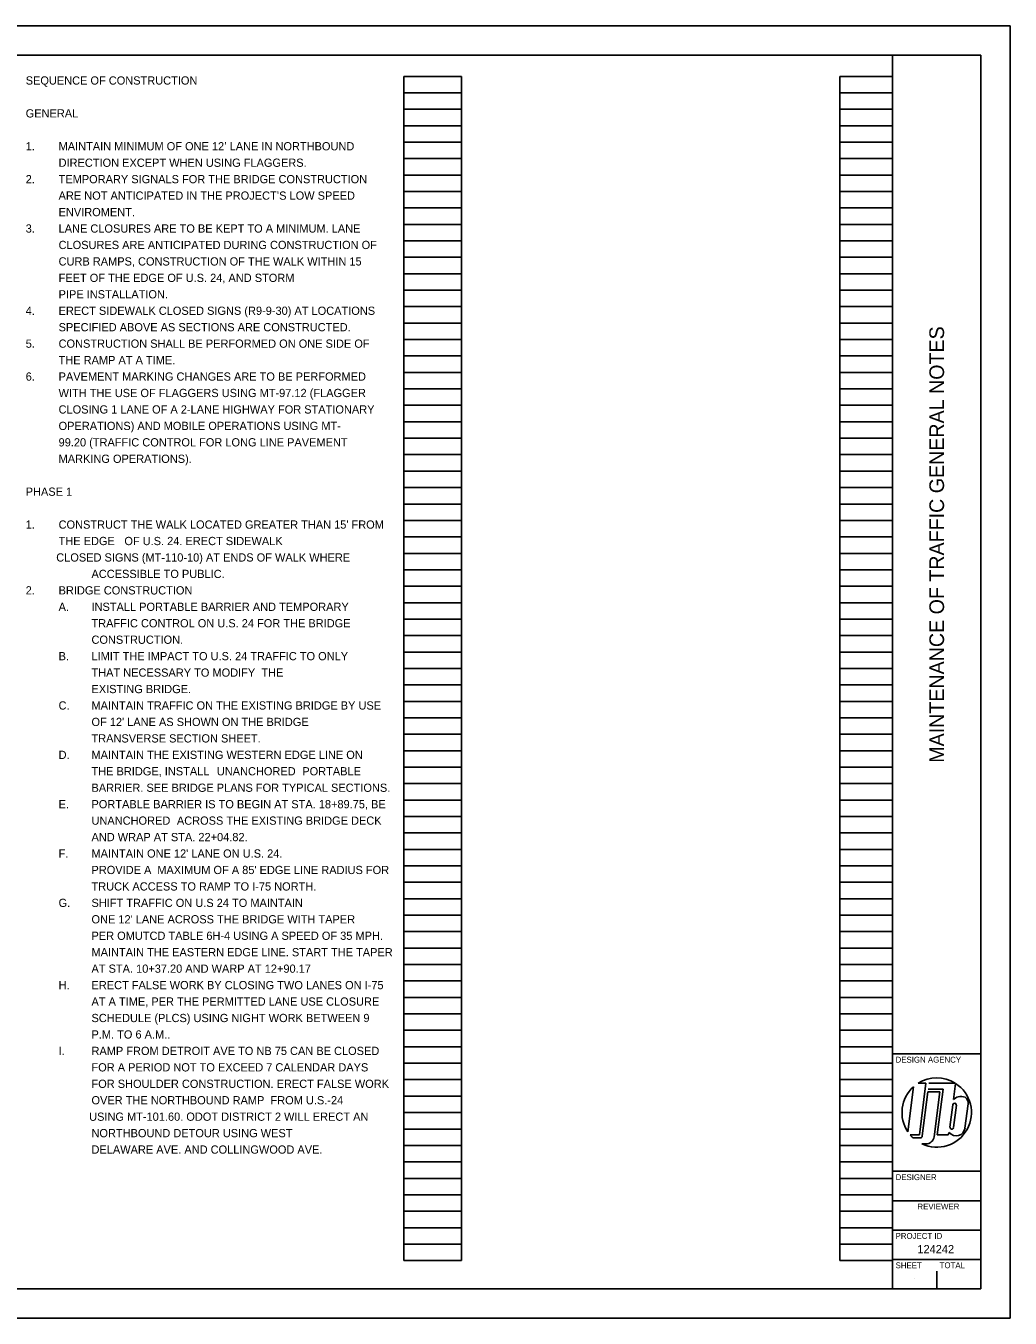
# Model space of a CAD drawing. Extents: x -43 to -9, y 0 to 22.
# Drawn here: x -25.8 to -9.05, y 0 to 22 of the extents above; entities that cross this region are included whole.
import ezdxf

# ---------------------------------------------------------------- set-up
doc = ezdxf.new("R2010")
doc.units = 0
for name, color, linetype in [('SC_Scratch1', 7, 'Continuous'), ('SC_Scratch2', 7, 'Continuous'), ('SH_Text', 7, 'Continuous')]:
    doc.layers.add(name, color=color, linetype=linetype)

msp = doc.modelspace()

# ---------------------------------------------------------------- linework, layer by layer
at = {"layer": 'SC_Scratch1'}
for p, q in [((-19.367, 0.98), (-19.367, 21.14)), ((-19.367, 21.14), (-18.387, 21.14)), ((-18.387, 0.98), (-18.387, 21.14)), ((-11.947, 0.98), (-11.947, 21.14)), ((-11.947, 21.14), (-11.047, 21.14)), ((-11.047, 0.98), (-11.047, 21.14)), ((-19.367, 20.86), (-18.387, 20.86)), ((-11.947, 20.86), (-11.047, 20.86)), ((-19.367, 20.58), (-18.387, 20.58)), ((-11.947, 20.58), (-11.047, 20.58)), ((-19.367, 20.3), (-18.387, 20.3)), ((-11.947, 20.3), (-11.047, 20.3)), ((-19.367, 20.02), (-18.387, 20.02)), ((-11.947, 20.02), (-11.047, 20.02)), ((-19.367, 19.74), (-18.387, 19.74)), ((-11.947, 19.74), (-11.047, 19.74)), ((-19.367, 19.46), (-18.387, 19.46)), ((-11.947, 19.46), (-11.047, 19.46)), ((-19.367, 19.18), (-18.387, 19.18)), ((-11.947, 19.18), (-11.047, 19.18)), ((-19.367, 18.9), (-18.387, 18.9)), ((-11.947, 18.9), (-11.047, 18.9)), ((-19.367, 18.62), (-18.387, 18.62)), ((-11.947, 18.62), (-11.047, 18.62)), ((-19.367, 18.34), (-18.387, 18.34)), ((-11.947, 18.34), (-11.047, 18.34)), ((-19.367, 18.06), (-18.387, 18.06)), ((-11.947, 18.06), (-11.047, 18.06)), ((-19.367, 17.78), (-18.387, 17.78)), ((-11.947, 17.78), (-11.047, 17.78)), ((-19.367, 17.5), (-18.387, 17.5)), ((-11.947, 17.5), (-11.047, 17.5)), ((-19.367, 17.22), (-18.387, 17.22)), ((-11.947, 17.22), (-11.047, 17.22)), ((-19.367, 16.94), (-18.387, 16.94)), ((-11.947, 16.94), (-11.047, 16.94)), ((-19.367, 16.66), (-18.387, 16.66)), ((-11.947, 16.66), (-11.047, 16.66)), ((-19.367, 16.38), (-18.387, 16.38)), ((-11.947, 16.38), (-11.047, 16.38)), ((-19.367, 16.1), (-18.387, 16.1)), ((-11.947, 16.1), (-11.047, 16.1)), ((-19.367, 15.82), (-18.387, 15.82)), ((-11.947, 15.82), (-11.047, 15.82)), ((-19.367, 15.54), (-18.387, 15.54)), ((-11.947, 15.54), (-11.047, 15.54)), ((-19.367, 15.26), (-18.387, 15.26)), ((-11.947, 15.26), (-11.047, 15.26)), ((-19.367, 14.98), (-18.387, 14.98)), ((-11.947, 14.98), (-11.047, 14.98)), ((-19.367, 14.7), (-18.387, 14.7)), ((-11.947, 14.7), (-11.047, 14.7)), ((-19.367, 14.42), (-18.387, 14.42)), ((-11.947, 14.42), (-11.047, 14.42)), ((-19.367, 14.14), (-18.387, 14.14)), ((-11.947, 14.14), (-11.047, 14.14)), ((-19.367, 13.86), (-18.387, 13.86)), ((-11.947, 13.86), (-11.047, 13.86)), ((-19.367, 13.58), (-18.387, 13.58)), ((-11.947, 13.58), (-11.047, 13.58)), ((-19.367, 13.3), (-18.387, 13.3)), ((-11.947, 13.3), (-11.047, 13.3)), ((-19.367, 13.02), (-18.387, 13.02)), ((-11.947, 13.02), (-11.047, 13.02)), ((-19.367, 12.74), (-18.387, 12.74)), ((-11.947, 12.74), (-11.047, 12.74)), ((-19.367, 12.46), (-18.387, 12.46)), ((-11.947, 12.46), (-11.047, 12.46)), ((-19.367, 12.18), (-18.387, 12.18)), ((-11.947, 12.18), (-11.047, 12.18)), ((-19.367, 11.9), (-18.387, 11.9)), ((-11.947, 11.9), (-11.047, 11.9)), ((-19.367, 11.62), (-18.387, 11.62)), ((-11.947, 11.62), (-11.047, 11.62)), ((-19.367, 11.34), (-18.387, 11.34)), ((-11.947, 11.34), (-11.047, 11.34)), ((-19.367, 11.06), (-18.387, 11.06)), ((-11.947, 11.06), (-11.047, 11.06)), ((-19.367, 10.78), (-18.387, 10.78)), ((-11.947, 10.78), (-11.047, 10.78)), ((-19.367, 10.5), (-18.387, 10.5)), ((-11.947, 10.5), (-11.047, 10.5)), ((-19.367, 10.22), (-18.387, 10.22)), ((-11.947, 10.22), (-11.047, 10.22)), ((-19.367, 9.94), (-18.387, 9.94)), ((-11.947, 9.94), (-11.047, 9.94)), ((-19.367, 9.66), (-18.387, 9.66)), ((-11.947, 9.66), (-11.047, 9.66)), ((-19.367, 9.38), (-18.387, 9.38)), ((-11.947, 9.38), (-11.047, 9.38)), ((-19.367, 9.1), (-18.387, 9.1)), ((-11.947, 9.1), (-11.047, 9.1)), ((-19.367, 8.82), (-18.387, 8.82)), ((-11.947, 8.82), (-11.047, 8.82)), ((-19.367, 8.54), (-18.387, 8.54)), ((-11.947, 8.54), (-11.047, 8.54)), ((-19.367, 8.26), (-18.387, 8.26)), ((-11.947, 8.26), (-11.047, 8.26)), ((-19.367, 7.98), (-18.387, 7.98)), ((-11.947, 7.98), (-11.047, 7.98)), ((-19.367, 7.7), (-18.387, 7.7)), ((-11.947, 7.7), (-11.047, 7.7)), ((-19.367, 7.42), (-18.387, 7.42)), ((-11.947, 7.42), (-11.047, 7.42)), ((-19.367, 7.14), (-18.387, 7.14)), ((-11.947, 7.14), (-11.047, 7.14)), ((-19.367, 6.86), (-18.387, 6.86)), ((-11.947, 6.86), (-11.047, 6.86)), ((-19.367, 6.58), (-18.387, 6.58)), ((-11.947, 6.58), (-11.047, 6.58)), ((-19.367, 6.3), (-18.387, 6.3)), ((-11.947, 6.3), (-11.047, 6.3)), ((-19.367, 6.02), (-18.387, 6.02)), ((-11.947, 6.02), (-11.047, 6.02)), ((-19.367, 5.74), (-18.387, 5.74)), ((-11.947, 5.74), (-11.047, 5.74)), ((-19.367, 5.46), (-18.387, 5.46)), ((-11.947, 5.46), (-11.047, 5.46)), ((-19.367, 5.18), (-18.387, 5.18)), ((-11.947, 5.18), (-11.047, 5.18)), ((-19.367, 4.9), (-18.387, 4.9)), ((-11.947, 4.9), (-11.047, 4.9)), ((-19.367, 4.62), (-18.387, 4.62)), ((-11.947, 4.62), (-11.047, 4.62)), ((-19.367, 4.34), (-18.387, 4.34)), ((-11.947, 4.34), (-11.047, 4.34)), ((-19.367, 4.06), (-18.387, 4.06)), ((-11.947, 4.06), (-11.047, 4.06)), ((-19.367, 3.78), (-18.387, 3.78)), ((-11.947, 3.78), (-11.047, 3.78)), ((-19.367, 3.5), (-18.387, 3.5)), ((-11.947, 3.5), (-11.047, 3.5)), ((-19.367, 3.22), (-18.387, 3.22)), ((-11.947, 3.22), (-11.047, 3.22)), ((-19.367, 2.94), (-18.387, 2.94)), ((-11.947, 2.94), (-11.047, 2.94)), ((-19.367, 2.66), (-18.387, 2.66)), ((-11.947, 2.66), (-11.047, 2.66)), ((-19.367, 2.38), (-18.387, 2.38)), ((-11.947, 2.38), (-11.047, 2.38)), ((-19.367, 2.1), (-18.387, 2.1)), ((-11.947, 2.1), (-11.047, 2.1)), ((-19.367, 1.82), (-18.387, 1.82)), ((-11.947, 1.82), (-11.047, 1.82)), ((-19.367, 1.54), (-18.387, 1.54)), ((-11.947, 1.54), (-11.047, 1.54)), ((-19.367, 1.26), (-18.387, 1.26)), ((-11.947, 1.26), (-11.047, 1.26)), ((-19.367, 0.98), (-18.387, 0.98)), ((-11.947, 0.98), (-11.047, 0.98))]:
    msp.add_line(p, q, dxfattribs=at)
at = {"layer": 'SC_Scratch2'}
for p, q in [((-11.047, 0.5), (-11.047, 21.5)), ((-11.047, 4.5), (-9.547, 4.5)), ((-10.615, 3.998), (-10.48, 3.998)), ((-10.48, 3.998), (-10.591, 3.118)), ((-10.43, 4), (-9.982, 4)), ((-9.977, 3.996), (-10.011, 3.72)), ((-10.691, 3.94), (-10.788, 3.171)), ((-10.543, 3.104), (-10.448, 3.855)), ((-10.448, 3.855), (-10.246, 3.855)), ((-10.19, 3.896), (-10.443, 3.896)), ((-10.246, 3.855), (-10.343, 3.089)), ((-10.289, 3.118), (-10.19, 3.896)), ((-10.023, 3.631), (-10.071, 3.25)), ((-10.011, 3.243), (-9.963, 3.624)), ((-9.764, 3.648), (-9.816, 3.237)), ((-10.297, 3.5), (-10.297, 3.5)), ((-10.591, 3.118), (-10.748, 3.118)), ((-10.1, 3.118), (-10.289, 3.118)), ((-10.083, 3.161), (-10.1, 3.118)), ((-10.7, 3.068), (-10.584, 3.068)), ((-10.482, 2.966), (-10.549, 2.966)), ((-11.047, 2.5), (-9.547, 2.5)), ((-11.047, 2), (-9.547, 2)), ((-11.047, 1.5), (-9.547, 1.5)), ((-11.047, 1), (-9.547, 1)), ((-10.672, 0.675), (-10.672, 0.675)), ((-10.297, 0.5), (-10.297, 0.8))]:
    msp.add_line(p, q, dxfattribs=at)
for points in [[(-43.047, 0), (-9.047, 0), (-9.047, 22), (-43.047, 22)], [(-41.547, 21.5), (-9.547, 21.5), (-9.547, 0.5), (-41.547, 0.5)]]:
    msp.add_lwpolyline(points, close=True, dxfattribs=at)
for centre, radius, start, end in [((-10.297, 3.5), 0.591, 57.726, 122.5688), ((-10.297, 3.5), 0.591, 244.7646, 57.1575), ((-10.297, 3.5), 0.591, 131.8253, 213.7822), ((-9.877, 3.586), 0.19, 105.9444, 135.0487), ((-9.883, 3.6), 0.175, 66.6782, 105.4185), ((-9.87, 3.669), 0.108, 349.2072, 58.7163), ((-9.993, 3.628), 0.0301, 352.3298, 173.2777), ((-10.297, 3.5), 0.591, 220.2786, 227.0158), ((-10.584, 3.109), 0.0417, 270, 352.8038), ((-10.482, 3.106), 0.141, 270, 352.8038), ((-9.965, 3.255), 0.151, 218.6264, 353.0883), ((-10.041, 3.246), 0.0301, 172.3335, 353.274)]:
    msp.add_arc(centre, radius, start, end, dxfattribs=at)

# ---------------------------------------------------------------- texts
msp.add_text('MAINTENANCE OF TRAFFIC GENERAL NOTES', height=0.25, rotation=90, dxfattribs=at).set_placement((-10.172, 9.455))
for s, height, p in [('DESIGN AGENCY', 0.1, (-10.997, 4.35)), ('DESIGNER', 0.1, (-10.997, 2.35)), ('REVIEWER', 0.1, (-10.625, 1.85)), ('PROJECT ID', 0.1, (-10.997, 1.35)), ('124242', 0.14, (-10.626, 1.105)), ('SHEET', 0.1, (-10.997, 0.85)), ('TOTAL', 0.1, (-10.247, 0.85))]:
    msp.add_text(s, height=height, dxfattribs=at).set_placement(p)
at = {"layer": 'SH_Text'}
for s, p in [('SEQUENCE OF CONSTRUCTION', (-25.807, 21)), ('GENERAL', (-25.807, 20.44)), ('1. ', (-25.807, 19.88)), ('MAINTAIN MINIMUM OF ONE 12’ LANE IN NORTHBOUND ', (-25.247, 19.88)), ('DIRECTION EXCEPT WHEN USING FLAGGERS. ', (-25.247, 19.6)), ('2. ', (-25.807, 19.32)), ('TEMPORARY SIGNALS FOR THE BRIDGE CONSTRUCTION ', (-25.247, 19.32)), ('ARE NOT ANTICIPATED IN THE PROJECT’S LOW SPEED ', (-25.247, 19.04)), ('ENVIROMENT.', (-25.247, 18.76)), ('3. ', (-25.807, 18.48)), ('LANE CLOSURES ARE TO BE KEPT TO A MINIMUM. LANE ', (-25.247, 18.48)), ('CLOSURES ARE ANTICIPATED DURING CONSTRUCTION OF ', (-25.247, 18.2)), ('CURB RAMPS, CONSTRUCTION OF THE WALK WITHIN 15 ', (-25.247, 17.92)), ('FEET OF THE EDGE OF U.S. 24, AND STORM ', (-25.247, 17.64)), ('PIPE INSTALLATION. ', (-25.247, 17.36)), ('4.', (-25.807, 17.08)), ('ERECT SIDEWALK CLOSED SIGNS (R9-9-30) AT LOCATIONS ', (-25.247, 17.08)), ('SPECIFIED ABOVE AS SECTIONS ARE CONSTRUCTED.', (-25.247, 16.8)), ('5.', (-25.807, 16.52)), ('CONSTRUCTION SHALL BE PERFORMED ON ONE SIDE OF     ', (-25.247, 16.52)), ('THE RAMP AT A TIME. ', (-25.247, 16.24)), ('6.', (-25.807, 15.96)), ('PAVEMENT MARKING CHANGES ARE TO BE PERFORMED ', (-25.247, 15.96)), ('WITH THE USE OF FLAGGERS USING MT-97.12 (FLAGGER ', (-25.247, 15.68)), ('CLOSING 1 LANE OF A 2-LANE HIGHWAY FOR STATIONARY  ', (-25.247, 15.4)), ('OPERATIONS) AND MOBILE OPERATIONS USING MT-', (-25.247, 15.12)), ('99.20 (TRAFFIC CONTROL FOR LONG LINE PAVEMENT ', (-25.247, 14.84)), ('MARKING OPERATIONS).', (-25.247, 14.56)), ('PHASE 1', (-25.807, 14)), ('1.', (-25.807, 13.44)), ("CONSTRUCT THE WALK LOCATED GREATER THAN 15' FROM      ", (-25.247, 13.44)), ('THE EDGE ', (-25.247, 13.16)), ('OF U.S. 24. ERECT SIDEWALK ', (-24.127, 13.16)), ('          CLOSED SIGNS (MT-110-10) AT ENDS OF WALK WHERE ', (-25.807, 12.88)), ('ACCESSIBLE TO PUBLIC.', (-24.687, 12.6)), ('2.', (-25.807, 12.32)), ('BRIDGE CONSTRUCTION', (-25.247, 12.32)), ('A.', (-25.247, 12.04)), ('INSTALL PORTABLE BARRIER AND TEMPORARY ', (-24.687, 12.04)), ('TRAFFIC CONTROL ON U.S. 24 FOR THE BRIDGE ', (-24.687, 11.76)), ('CONSTRUCTION. ', (-24.687, 11.48)), ('B.', (-25.247, 11.2)), ('LIMIT THE IMPACT TO U.S. 24 TRAFFIC TO ONLY ', (-24.687, 11.2)), ('THAT NECESSARY TO MODIFY  THE ', (-24.687, 10.92)), ('EXISTING BRIDGE. ', (-24.687, 10.64)), ('C.', (-25.247, 10.36)), ('MAINTAIN TRAFFIC ON THE EXISTING BRIDGE BY USE ', (-24.687, 10.36)), ("OF 12' LANE AS SHOWN ON THE BRIDGE ", (-24.687, 10.08)), ('TRANSVERSE SECTION SHEET. ', (-24.687, 9.8)), ('D.', (-25.247, 9.52)), ('MAINTAIN THE EXISTING WESTERN EDGE LINE ON ', (-24.687, 9.52)), ('THE BRIDGE, INSTALL ', (-24.687, 9.24)), ('UNANCHORED', (-22.553, 9.24)), (' PORTABLE ', (-21.15, 9.24)), ('BARRIER. SEE BRIDGE PLANS FOR TYPICAL SECTIONS. ', (-24.687, 8.96)), ('E.', (-25.247, 8.68)), ('PORTABLE BARRIER IS TO BEGIN AT STA. 18+89.75, BE ', (-24.687, 8.68)), ('UNANCHORED', (-24.687, 8.4)), (' ACROSS THE EXISTING BRIDGE DECK ', (-23.285, 8.4)), ('AND WRAP AT STA. 22+04.82.', (-24.687, 8.12)), ('F.', (-25.247, 7.84)), ("MAINTAIN ONE 12' LANE ON U.S. 24. ", (-24.687, 7.84)), ('PROVIDE A ', (-24.687, 7.56)), ("MAXIMUM OF A 85' EDGE LINE RADIUS FOR ", (-23.567, 7.56)), ('TRUCK ACCESS TO RAMP TO I-75 NORTH.', (-24.687, 7.28)), ('G.', (-25.247, 7)), ('SHIFT TRAFFIC ON U.S 24 TO MAINTAIN ', (-24.687, 7)), ("ONE 12' LANE ACROSS THE BRIDGE WITH TAPER ", (-24.687, 6.72)), ('PER OMUTCD TABLE 6H-4 USING A SPEED OF 35 MPH. ', (-24.687, 6.44)), ('MAINTAIN THE EASTERN EDGE LINE. START THE TAPER ', (-24.687, 6.16)), ('AT STA. 10+37.20 AND WARP AT 12+90.17', (-24.687, 5.88)), ('H.', (-25.247, 5.6)), ('ERECT FALSE WORK BY CLOSING TWO LANES ON I-75 ', (-24.687, 5.6)), ('AT A TIME, PER THE PERMITTED LANE USE CLOSURE ', (-24.687, 5.32)), ('SCHEDULE (PLCS) USING NIGHT WORK BETWEEN 9 ', (-24.687, 5.04)), ('P.M. TO 6 A.M..', (-24.687, 4.76)), ('RAMP FROM DETROIT AVE TO NB 75 CAN BE CLOSED ', (-24.687, 4.48)), ('I.', (-25.247, 4.48)), ('FOR A PERIOD NOT TO EXCEED 7 CALENDAR DAYS ', (-24.687, 4.2)), ('FOR SHOULDER CONSTRUCTION. ERECT FALSE WORK ', (-24.687, 3.92)), ('OVER THE NORTHBOUND RAMP  FROM U.S.-24 ', (-24.687, 3.64)), ('          USING MT-101.60. ODOT DISTRICT 2 WILL ERECT AN', (-25.247, 3.36)), ('NORTHBOUND DETOUR USING WEST', (-24.687, 3.08)), ('DELAWARE AVE. AND COLLINGWOOD AVE. ', (-24.687, 2.8))]:
    msp.add_text(s, height=0.14, dxfattribs=at).set_placement(p)

doc.saveas('drawing.dxf')
